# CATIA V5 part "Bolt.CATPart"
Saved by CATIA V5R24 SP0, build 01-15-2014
Part number: Bolt
Bounding box of the stored display mesh (mm): x -5.774 to 5.774, y -5 to 5, z -38 to 5
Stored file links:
  C:\Users\minsi\Google 드라이브\CDL_2019\00_CLASS\00_CAD\기말고사\DMU\Bolt.CATPart
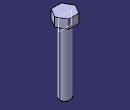
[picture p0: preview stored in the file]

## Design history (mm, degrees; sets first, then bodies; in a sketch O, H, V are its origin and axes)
Body1 (main body)
  Sketch1 on xy-plane, origin (0, 0, 0), H (1, 0, 0), V (0, 1, 0)
    point P1 (2.8868, 5)
    point P2 (-2.8868, 5)
    point P3 (-5.7735, 0)
    point P4 (-2.8868, -5)
    point P5 (2.8868, -5)
    point P6 (5.7735, 0)
    point P7 (0, 5)
    line L1 (2.8868, 5) -> (-2.8868, 5)
    line L2 (-2.8868, 5) -> (-5.7735, 0)
    line L3 (-5.7735, 0) -> (-2.8868, -5)
    line L4 (-2.8868, -5) -> (2.8868, -5)
    line L5 (2.8868, -5) -> (5.7735, 0)
    line L6 (5.7735, 0) -> (2.8868, 5)
    construction line L7 (0, 0) -> (0, 5)
    construction circle A1 centre (0, 0) radius 5.7735
    construction arc A2 centre (2.8868, -5) radius 5.7735 from (-2.8868, -5) to (5.7735, 0) cw
    construction arc A3 centre (-2.8868, 5) radius 5.7735 from (-5.7735, 0) to (2.8868, 5) ccw
    distance L1 L4 = 10
    vertical: L7 V
    coincidence: A1 P1, A1 P2, A1 P3, A1 P4, A1 P5, A1 P6, A2 O, A3 O
    midpoint: P7 L1
    parallelism: L1 L4, L2 L5
  Pad1: profile Sketch1, direction (0, 0, 1), length 5
  Sketch2 on start face of Pad1, origin (0, 0, 0), H (1, 0, 0), V (0, -1, 0)
    circle A1 centre (0, 0) radius 3
    radius A1 = 3
  Pad2: profile Sketch2, direction (0, 0, -1), length 38
  Chamfer1: length 1, angle 45, on edge [face of Pad2 from Sketch2.A1 | end face of Pad2]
